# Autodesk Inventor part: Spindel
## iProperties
Created: 2009-10
Part Number: Spindel
Cost Center: 0 kg
Material: 3.3206 AlMgSi0,5
Description: Startmodell Bauteil
Document SubType Name: Modeling
Designer: BoseDa
Authority: 0 mm^3
Manufacturer: Standard
Standards Organization: Custom
Density: 2.66 g/cm^3
Company: Grenzebach BSH
Author: BoseDa
FileName: Norm
SaveDate: 2008-11-23
SaveTime: 16:30
TotalMass: 0 kg
TotalVolume: 0 mm^3
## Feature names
1. Extrusion2
2. Extrusion3
